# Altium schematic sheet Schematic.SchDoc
size A4; SheetNumber: 1; SheetTotal: 1
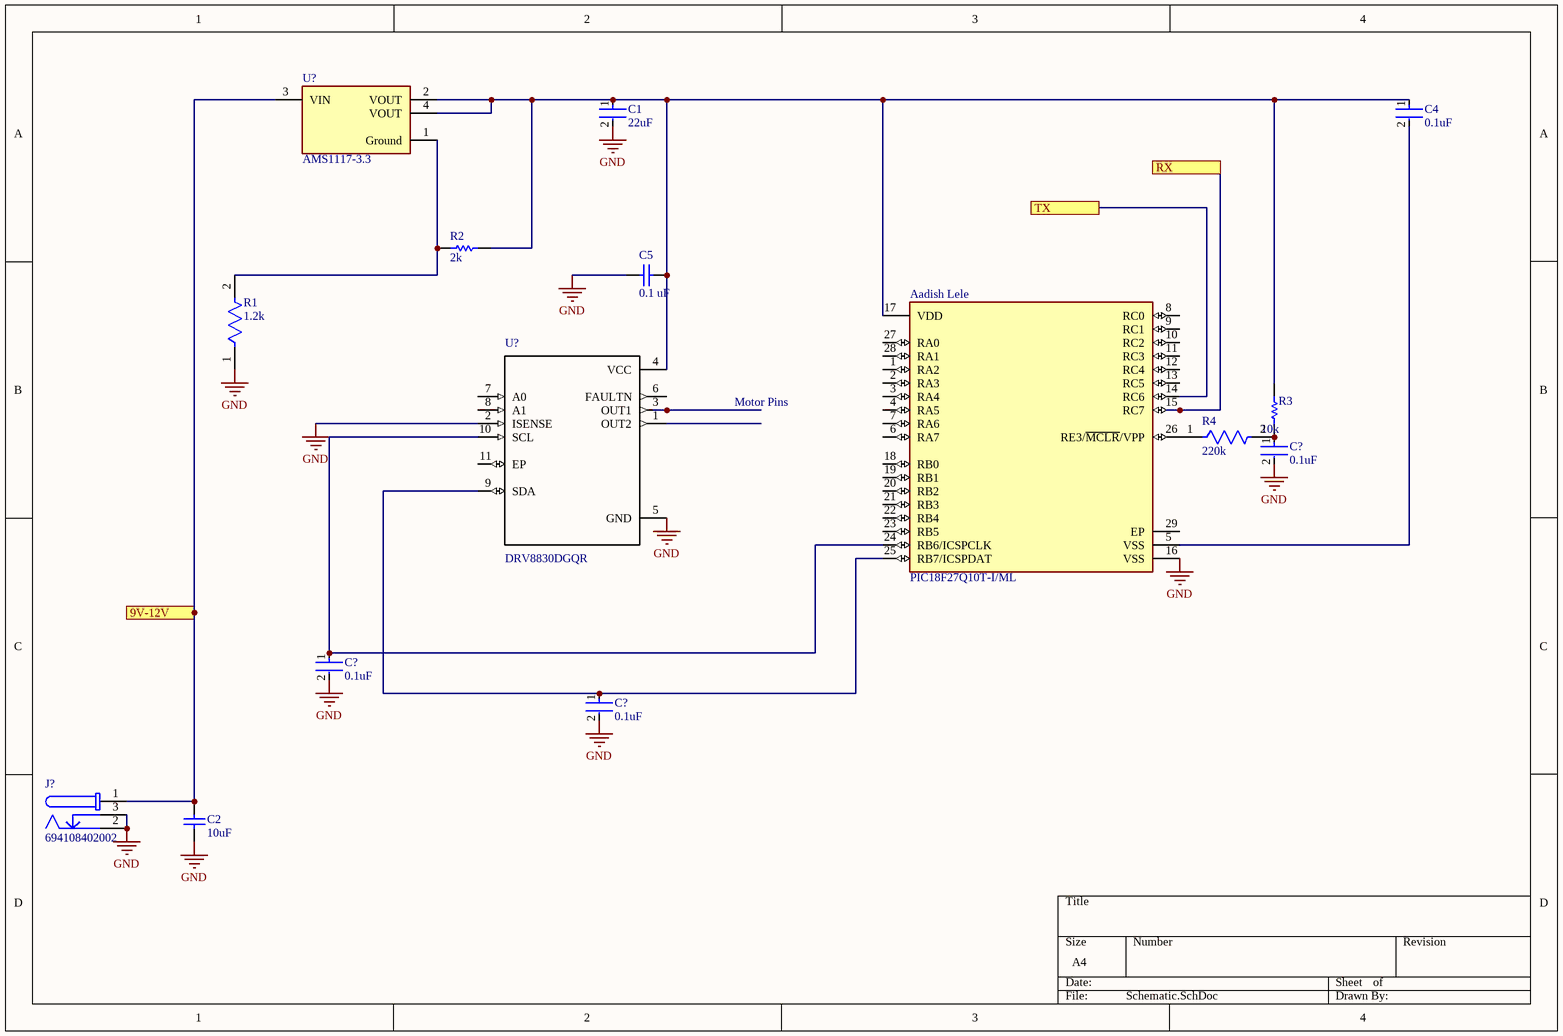
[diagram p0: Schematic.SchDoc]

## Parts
(Parts that share a designator on the sheet are numbered #1, #2 ... from top to bottom, then left to right.)
Aadish_Lele  PIC18F27Q10T-I/ML  [FP-C04-105-MFG]
C1  22uF  [FP-GRM21B-0_15-MFG]
C2  10uF  [CAPC3216X180X55LL20T25]
C4  0.1uF  [FP-C0603C-CF-MFG]
C5  0.1 uF  [MURA-0603_H_0.9_M]
C?#1  0.1uF  [FP-C0603C-CF-MFG]
C?#2  0.1uF  [FP-C0603C-CF-MFG]
C?#3  0.1uF  [FP-C0603C-CF-MFG]
J?  694108402002  [694108402002]
R1  1.2k  [FP-RG1005-IPC_A]
R2  2k  [RESC1005X40X25ML05T10]
R3  10k  [RESC1609X50X30NL8T20]
R4  220k  [FP-ERA3A-MFG]
U?#1  AMS1117-3.3  [FP-AMS1117-IPC_C]
U?#2  DRV8830DGQR  [*IC_XTR111AIDGQR]

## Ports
9V-12V, RX, TX

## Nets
GND: Aadish_Lele.16(VSS) C1.2 C2.1 C5.1 C?#1.2 C?#2.2 C?#3.2 J?.2 J?.3 R1.1 U?#2.2(ISENSE) U?#2.5(GND)
9V-12V: C2.2 J?.1 U?#1.3(VIN) ; port 9V-12V
RX: Aadish_Lele.15(RC7) ; port RX
TX: Aadish_Lele.14(RC6) ; port TX
NetAadish_Lele_5: Aadish_Lele.5(VSS) C4.2
NetAadish_Lele_17: Aadish_Lele.17(VDD) C1.1 C4.1 C5.2 R2.2 R3.2 U?#1.2(VOUT) U?#1.4(VOUT) U?#2.4(VCC)
NetAadish_Lele_24: Aadish_Lele.24(RB6/ICSPCLK) C?#2.1 U?#2.10(SCL)
NetAadish_Lele_25: Aadish_Lele.25(RB7/ICSPDAT) C?#3.1 U?#2.9(SDA)
NetAadish_Lele_26: Aadish_Lele.26(RE3/~{MCLR}/VPP) R4.1
NetC?#1_1: C?#1.1 R3.1 R4.2
NetR1_2: R1.2 R2.1 U?#1.1(Ground)

Not connected (* = marked no-connect by the designer): Aadish_Lele 1(RA2) 2(RA3) 3(RA4) 4(RA5) 6(RA7) 7(RA6) 8(RC0) 9(RC1) 10(RC2) 11(RC3) 12(RC4) 13(RC5) 18(RB0) 19(RB1) 20(RB2) 21(RB3) 22(RB4) 23(RB5) 27(RA0) 28(RA1) 29(EP); U?#2 1(OUT2) 3(OUT1) 6(FAULTN) 7(A0) 8(A1) 11(EP)

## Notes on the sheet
- Motor Pins

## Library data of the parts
Aadish_Lele = CMP-00252-96705243-1: PIC18F27Q10T-I/ML 8-bit PIC MCU, 128 KB, 3615 Bytes, 64 MHz, 1.8 to 5.5V, QFN-28, RoHS; Number of Timers/Counters: 4; Number of UART Channels: 2; Frequency: 64MHz; Number of I/Os: 25; Data Bus Width: 8b; Number of ADC Channels: 24; Min Supply Voltage: 1.8V; Number of A/D Converters: 1; Max Junction Temperature (Tj): 150°C; RAM Size: 3.5kB; Memory Type: FLASH; Memory Size: 128kB; Interface: I2C, LIN, SMBus, SPI, USART
C1 = CMP-2007-03385-2: Chip Multilayer Ceramic Capacitors for General Purpose, 0805, 22uF, X5R, 15%, 20%, 6.3V
C2 = CMP-2000-06345-1: Chip Capacitor, 10 uF, +/- 10%, 10 V, -55 to 85 degC, 1206 (3216 Metric), RoHS, Tape and Reel; Manufacturer: Murata; Voltage - Rated: 10V; Other Names: 490-1820-6; Capacitance: 10µF; Product Training Modules: High-CapMultilayerCeramicCapacitors; Catalog Drawings: GRMSeries_1206_1.6; Featured Product: GA3SafetyRecognizedCapsandHi-CapMLCC; Temperature Coefficient: X5R; Online Catalog: GRMSeries
C4 C?#1-C?#3 = CMP-2006-03061-2: CAP CER 0.1UF 50V X7R 0603; Manufacturer: KEMET; Manufacturer Part Number: C0603C104K5RACTU; Tolerance: 0.1; Description: C0603 0.10 μF X7R 30ppm/°C 10.00% 50 V; Temperature Coefficient: 30ppm/°C; Material: Ceramic; Automotive Grade: Grade 1; Value: 0.10 μF
C5 = CMP-2000-05253-1: CAP, Ceramic, 0.1 uF, 10%, 16 V, 0603, RoHS, Tape and Reel; Manufacturer: Murata; Capacitance - pF: 100000pF; Case Length: 1.6mm; Voltage Rating DC: 16V; Brand: MurataElectronics; Temperature Coefficient / Code: +/-15%; Case Width: 0.8mm; Type: GeneralPurposeMLCC; Capacitance: 0.1uF; Dielectric: X7R; Capacitance - nF: 100nF
J? = CMP-1502-00191-2: NexarPartId: 52676103; Voltage Rating (DC): 20V; Current Rating: 3A; Insulation Resistance: 100MΩ; Shielding: Unshielded; Connector Type: Power; Gender: Male
R1 = CMP-28537-013188-1: Automotive Metal Thin Film Chip Resistor, 0402, 1.2kΩ, 0.1%, 10ppm/°C, 0.0625W, 75V; Power Rating: 63mW; Voltage Rating (DC): 25V; Resistance: 1.2kR
R2 = CMP-2002-07972-1: Part Number: RC0402JR-072KL; Manufacturer: Yageo / Phycomp
R3 = CMP-1666-00005-4: Chip Resistor, 10 KOhm, +/- 1%, 100 mW, -55 to 155 degC, 0603 (1608 Metric), RoHS, Tape and Reel; Manufacturer: Vishay Semiconductor; Voltage Rating: 75 V
R4 = CMP-2000-00957-2: NexarPartId: 1251723; Voltage Rating (DC): 75V; Temperature Coefficient: 25ppm/°C; Resistance: 220kΩ; Tolerance: 0.1%; Max Power Dissipation: 100mW
U?#1 = CMP-209535-000001-1: LDO Voltage Regulators 1A, 3.3V; Manufacturer: Advanced Monolithic Systems; Dropout Voltage: 1.1V; Output Type: Fixed; Nominal Supply Current: 5mA; Max Power Dissipation: 1.2W; Max Supply Voltage: 15V; Number Of Outputs: 1; Standoff Height: 0.64mm; Max Junction Temp: +125°C
U?#2 = DRV8830DGQR: 7-V, 1-A H-bridge motor driver with speed regulation and I2C control; MF: Texas Instruments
